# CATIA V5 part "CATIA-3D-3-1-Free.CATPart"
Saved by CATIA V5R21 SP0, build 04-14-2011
Part number: CATIA-3D-3-1-Free
Bounding box of the stored display mesh (mm): x -80 to 20, y 0 to 50, z -20 to 44.497
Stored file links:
  C:\Users\Rasoul Mohammadi\Desktop\CATIA-Free\3D\CATIA-3D-3-1-Free.CATPart
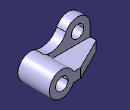
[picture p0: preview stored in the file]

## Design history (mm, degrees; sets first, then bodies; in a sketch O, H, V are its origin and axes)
Body1 (main body)
  Sketch1 on zx-plane, origin (0, 0, 0), H (-1, 0, 0), V (0, 0, 1)
    arc A1 centre (0, 0) radius 20 from (18.5405, 7.5) to (18.5405, -7.5) ccw
    line L1 (18.5405, 7.5) -> (80, 7.5)
    line L2 (80, 7.5) -> (80, -7.5)
    line L3 (80, -7.5) -> (18.5405, -7.5)
    circle A2 centre (0, 0) radius 10
    radius A1 = 20
    distance L2 V = 80
    length L2 = 15
    radius A2 = 10
    horizontal: L1 H, L3 H
    vertical: L2 V
    symmetry: L1 L3 H
  Pad1: profile Sketch1, direction (0, 1, 0), length 50
  Sketch2 on zx-plane, origin (0, 0, 0), H (-1, 0, 0), V (0, 0, 1)
    projected line E1 (80, 7.5) -> (18.5405, 7.5) from edge [face of Pad1 from Sketch1.L1 | end face of Pad1]
    point P2 (18.5405, 7.5)
    projected arc E2 centre (0, 0) radius 20 from (18.5405, 7.5) to (18.5405, -7.5) ccw from edge [face of Pad1 from Sketch1.A1 | end face of Pad1]
    projected arc E3 centre (0, 0) radius 20 from (18.5405, 7.5) to (7.2896, 18.6242) ccw from edge [face of Pad1 from Sketch1.A1 | end face of Pad1]
    point P3 (18.5405, 7.5)
    arc A1 centre (60, 24.5) radius 20 from (80, 24.5) to (41.7577, 32.6987) ccw
    point P5 (60, 24.5)
    line L1 (80, 24.5) -> (80, 7.5)
    arc A2 centre (17.1306, 43.7669) radius 27 from (41.7577, 32.6987) to (7.2896, 18.6242) cw
    point P9 (7.2896, 18.6242)
    circle A3 centre (60, 24.5) radius 10
    radius A1 = 20
    radius A2 = 27
    distance P5 E1 = 17
    radius A3 = 10
    coincidence: P9 E2, P2 P3
    vertical: L1 V
    tangency: A1 L1, A2 A1, A2 E2
  Pad2: profile Sketch2, direction (0, 1, 0), length 15
  Chamfer1: length 25, second length 50, on edge [face of Pad2 | end face of Pad1]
